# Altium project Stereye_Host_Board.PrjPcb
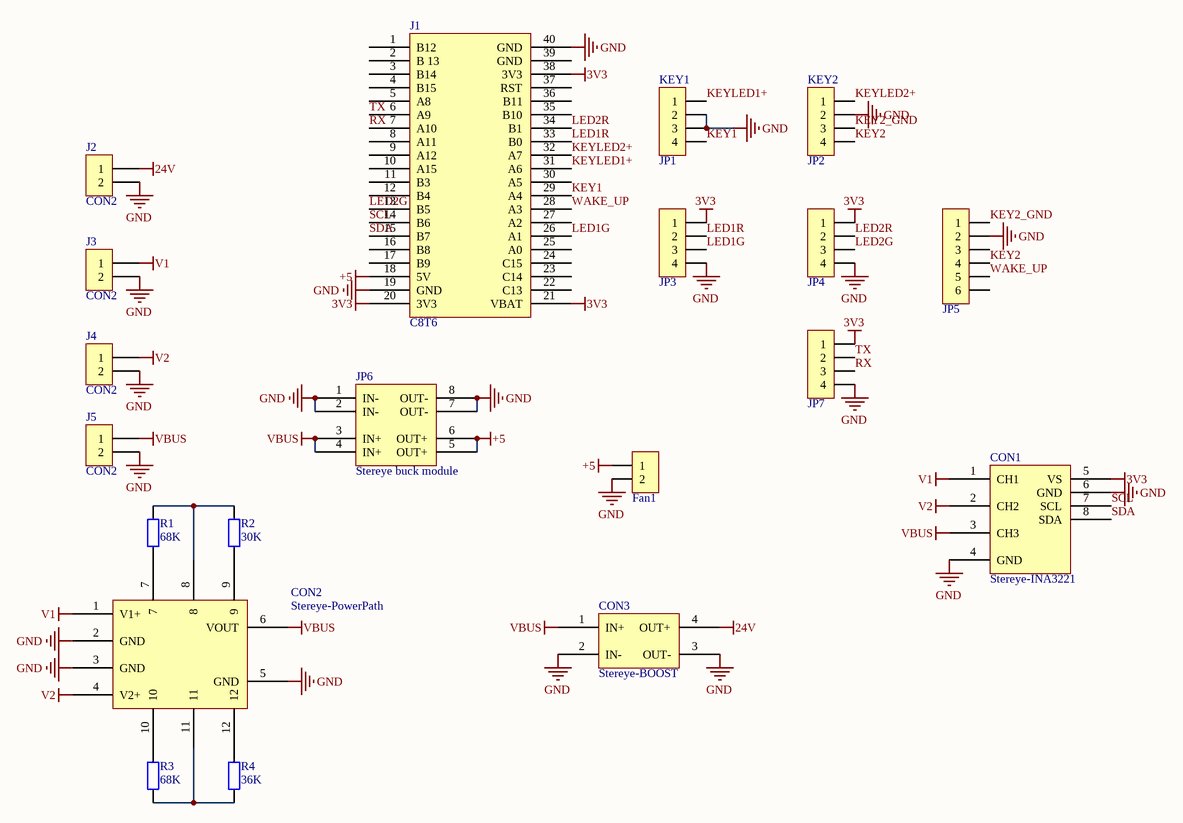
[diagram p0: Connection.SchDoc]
1 sheet, 20 parts. Net scope: global (net labels, ports and power ports of the same name join across sheets).
Board file: HostBoard_V2.PcbDoc

## Sheet Connection.SchDoc
size A4

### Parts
CON1  Stereye-INA3221  [STEREYE-INA3221]
CON2  Stereye-PowerPath  [STEREYE-PowerPath]
CON3  Stereye-BOOST  [STEREYE-BOOST]
Fan1  HDR-1X2  [PH2.0-WS-2P]  (value not drawn)
J1  C8T6  [C8T6]
J2  CON2  [XT30 - F]
J3  CON2  [XT30 - M]
J4  CON2  [XT30 - M]
J5  CON2  [XT30 - F]
JP1  KEY1  [MX 1.25-LS-4P]
JP2  KEY2  [MX 1.25-LS-4P]
JP3  HDR-1X4  [MX 1.25-LS-4P]  (value not drawn)
JP4  HDR-1X4  [MX 1.25-LS-4P]  (value not drawn)
JP5  HDR-1X6  [SH1.0]  (value not drawn)
JP6  Stereye buck module  [Stereye buck module]
JP7  HDR-1X4  [MX 1.25-LS-4P]  (value not drawn)
R1  68K  [R 0603_L]
R2  30K  [R 0603_L]
R3  68K  [R 0603_L]
R4  36K  [R 0603_L]

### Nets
3V3: CON1.5(VS) J1.20(3V3) J1.21(VBAT) J1.38(3V3) JP3.1 JP4.1 JP7.1
24V: CON3.4(OUT+) J2.1
+5: Fan1.1 J1.18(5V) JP6.5(OUT+) JP6.6(OUT+)
GND: CON1.4(GND) CON1.6(GND) CON2.2(GND) CON2.3(GND) CON2.5(GND) CON3.2(IN-) CON3.3(OUT-) Fan1.2 J1.19(GND) J1.40(GND) J2.2 J3.2 J4.2 J5.2 JP1.2 JP1.3 JP2.2 JP3.4 JP4.4 JP5.2 JP6.1(IN-) JP6.2(IN-) JP6.7(OUT-) JP6.8(OUT-) JP7.4
V1: CON1.1(CH1) CON2.1(V1+) J3.1
V2: CON1.2(CH2) CON2.4(V2+) J4.1
VBUS: CON1.3(CH3) CON2.6(VOUT) CON3.1(IN+) J5.1 JP6.3(IN+) JP6.4(IN+)
KEY1: J1.29(A4) JP1.4
KEY2: JP2.4 JP5.4
KEY2_GND: JP2.3 JP5.1
KEYLED1+: J1.31(A6) JP1.1
KEYLED2+: J1.32(A7) JP2.1
LED1G: J1.26(A1) JP3.3
LED1R: J1.33(B0) JP3.2
LED2G: J1.13(B5) JP4.3
LED2R: J1.34(B1) JP4.2
RX: J1.7(A10) JP7.3
SCL: CON1.7(SCL) J1.14(B6)
SDA: CON1.8(SDA) J1.15(B7)
TX: J1.6(A9) JP7.2
WAKE_UP: J1.28(A3) JP5.5
NetCON2_7: CON2.7 R1.1
NetCON2_8: CON2.8 R1.2 R2.2
NetCON2_9: CON2.9 R2.1
NetCON2_10: CON2.10 R3.2
NetCON2_11: CON2.11 R3.1 R4.1
NetCON2_12: CON2.12 R4.2

Not connected (* = marked no-connect by the designer): J1 1(B12) 2(B_13) 3(B14) 4(B15) 5(A8) 8(A11) 9(A12) 10(A15) 11(B3) 12(B4) 16(B8) 17(B9) 22(C13) 23(C14) 24(C15) 25(A0) 27(A2) 30(A5) 35(B10) 36(B11) 37(RST) 39(GND); JP5 3 6

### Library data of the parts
Fan1 = Header 2: 2P接插件; 版权归属: 封装库来自淘宝 ID：黄晶宝石
J1 = C8T6: C8T6转接
JP1-JP4 JP7 = Header 4: 4P接插件; 版权归属: 封装库来自淘宝 ID：黄晶宝石
JP5 = Header 6: 6P接插件; 版权归属: 封装库来自淘宝 ID：黄晶宝石
R1-R4 = R: 贴片电阻; 版权归属: 来自淘宝 ID：黄晶宝石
